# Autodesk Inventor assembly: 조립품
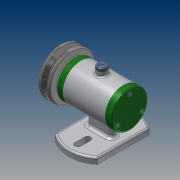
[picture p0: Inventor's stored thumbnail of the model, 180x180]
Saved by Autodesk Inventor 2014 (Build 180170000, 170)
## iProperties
Created: 2017-12
Part Number: 조립품
Document SubType Name: Assembly
Designer: user
Author: user
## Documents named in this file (14)
- C:\Users\user\Desktop\471208V1012[1]\조립품.iam
- C:\Users\user\Desktop\471208V1012[1]\본체.ipt
- C:\Users\user\Desktop\471208V1012[1]\앞커버.ipt
- C:\Users\user\Desktop\471208V1012[1]\오일 실 15 25 7.ipt
- C:\Users\user\Desktop\471208V1012[1]\와셔 8x17.ipt
- C:\Users\user\Desktop\471208V1012[1]\축.ipt
- C:\Users\user\Desktop\471208V1012[1]\키 3 x 3 x 12.ipt
- C:\Users\user\Desktop\471208V1012[1]\V벨트풀리.ipt
- C:\Users\user\Desktop\471208V1012[1]\고무캡.ipt
- C:\Users\user\Desktop\471208V1012[1]\너트 M 8.ipt
- C:\Users\user\Desktop\471208V1012[1]\뒤커버.ipt
- C:\Users\user\Desktop\471208V1012[1]\베어링 15 x 32 x 9.ipt
- C:\Users\user\Desktop\471208V1012[1]\볼트 M4 x 12.ipt
- C:\Users\user\Desktop\471208V1012[1]\스프링와셔 8.ipt
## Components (2 placed, 2 different names)
1. V벨트풀리:1 — 각도:1
2. 고무캡:1
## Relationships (1: Angle 1)
- 각도:1 [Angle]: V벨트풀리:1
